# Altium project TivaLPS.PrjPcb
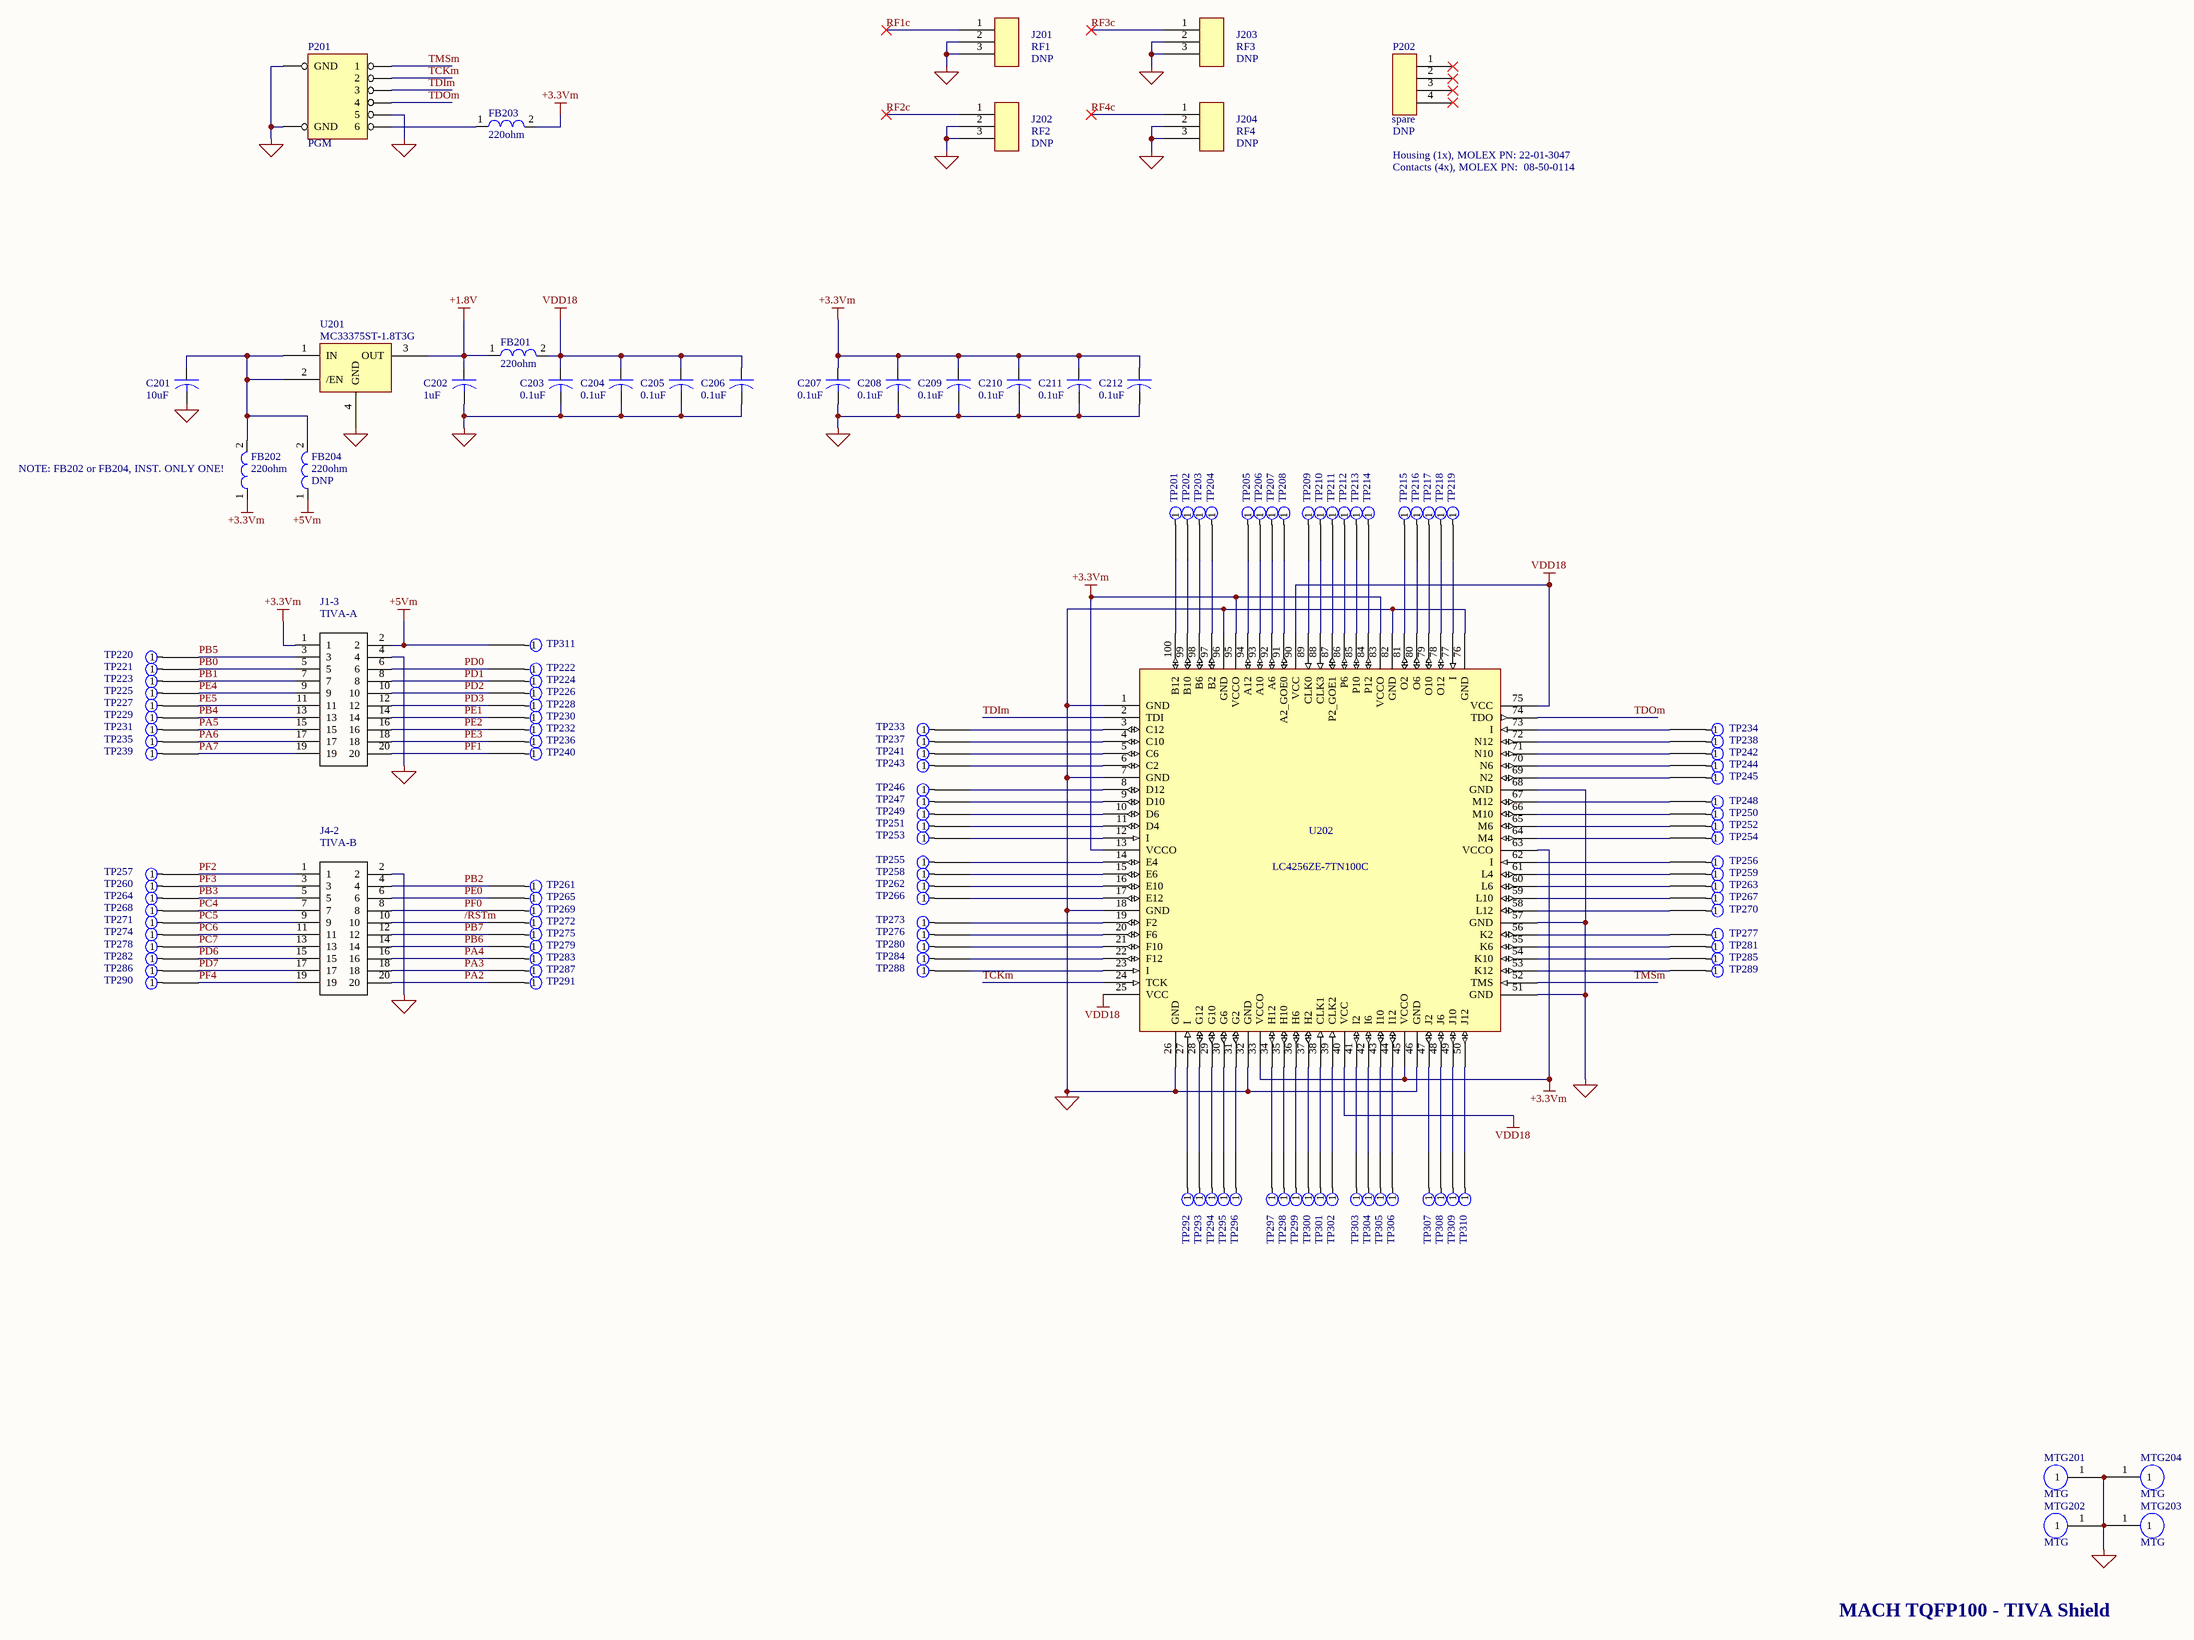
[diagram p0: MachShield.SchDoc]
1 sheet, 141 parts. Net scope: global (net labels, ports and power ports of the same name join across sheets).
Board file: TivaLPS.PcbDoc

## Sheet MachShield.SchDoc
size C

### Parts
C201  10uF  [0805]
C202  1uF  [0805]
C203  0.1uF  [0402]
C204  0.1uF  [0402]
C205  0.1uF  [0402]
C206  0.1uF  [0402]
C207  0.1uF  [0402]
C208  0.1uF  [0402]
C209  0.1uF  [0402]
C210  0.1uF  [0402]
C211  0.1uF  [0402]
C212  0.1uF  [0402]
FB201  220ohm  [0805]
FB202  220ohm  [0805]
FB203  220ohm  [0805]
FB204  220ohm  [0805]
J1-3  TIVA-A  [2X10_PADS]
J4-2  TIVA-B  [2X10_PADS]
J201  RF1  [CONN_SMA_EDGE_062]
J202  RF2  [CONN_SMA_EDGE_062]
J203  RF3  [CONN_SMA_EDGE_062_installed]
J204  RF4  [CONN_SMA_EDGE_062_installed]
MTG201  MTG  [MTG_125]  (no BOM)
MTG202  MTG  [MTG_125]  (no BOM)
MTG203  MTG  [MTG_125]  (no BOM)
MTG204  MTG  [MTG_125]  (no BOM)
P201  PGM  [CON_1.25MM_6P]
P202  spare  [MOLEX-04]
TP201  100  [TP]  (value not drawn)  (no BOM)
TP202  99  [TP]  (value not drawn)  (no BOM)
TP203  98  [TP]  (value not drawn)  (no BOM)
TP204  97  [TP]  (value not drawn)  (no BOM)
TP205  94  [TP]  (value not drawn)  (no BOM)
TP206  93  [TP]  (value not drawn)  (no BOM)
TP207  92  [TP]  (value not drawn)  (no BOM)
TP208  91  [TP]  (value not drawn)  (no BOM)
TP209  89  [TP]  (value not drawn)  (no BOM)
TP210  88  [TP]  (value not drawn)  (no BOM)
TP211  87  [TP]  (value not drawn)  (no BOM)
TP212  86  [TP]  (value not drawn)  (no BOM)
TP213  85  [TP]  (value not drawn)  (no BOM)
TP214  84  [TP]  (value not drawn)  (no BOM)
TP215  81  [TP]  (value not drawn)  (no BOM)
TP216  80  [TP]  (value not drawn)  (no BOM)
TP217  79  [TP]  (value not drawn)  (no BOM)
TP218  78  [TP]  (value not drawn)  (no BOM)
TP219  77  [TP]  (value not drawn)  (no BOM)
TP220  PB5  [TP-TH]  (value not drawn)  (no BOM)
TP221  PB0  [TP-TH]  (value not drawn)  (no BOM)
TP222  PD0  [TP-TH]  (value not drawn)  (no BOM)
TP223  PB1  [TP-TH]  (value not drawn)  (no BOM)
TP224  PD1  [TP-TH]  (value not drawn)  (no BOM)
TP225  PE4  [TP-TH]  (value not drawn)  (no BOM)
TP226  PD2  [TP-TH]  (value not drawn)  (no BOM)
TP227  PE5  [TP-TH]  (value not drawn)  (no BOM)
TP228  PD3  [TP-TH]  (value not drawn)  (no BOM)
TP229  PB4  [TP-TH]  (value not drawn)  (no BOM)
TP230  PE1  [TP-TH]  (value not drawn)  (no BOM)
TP231  PA5  [TP-TH]  (value not drawn)  (no BOM)
TP232  PE2  [TP-TH]  (value not drawn)  (no BOM)
TP233  3  [TP]  (value not drawn)  (no BOM)
TP234  73  [TP]  (value not drawn)  (no BOM)
TP235  PA6  [TP-TH]  (value not drawn)  (no BOM)
TP236  PE3  [TP-TH]  (value not drawn)  (no BOM)
TP237  4  [TP]  (value not drawn)  (no BOM)
TP238  72  [TP]  (value not drawn)  (no BOM)
TP239  PA7  [TP-TH]  (value not drawn)  (no BOM)
TP240  PF1  [TP-TH]  (value not drawn)  (no BOM)
TP241  5  [TP]  (value not drawn)  (no BOM)
TP242  71  [TP]  (value not drawn)  (no BOM)
TP243  6  [TP]  (value not drawn)  (no BOM)
TP244  70  [TP]  (value not drawn)  (no BOM)
TP245  69  [TP]  (value not drawn)  (no BOM)
TP246  8  [TP]  (value not drawn)  (no BOM)
TP247  9  [TP]  (value not drawn)  (no BOM)
TP248  67  [TP]  (value not drawn)  (no BOM)
TP249  10  [TP]  (value not drawn)  (no BOM)
TP250  66  [TP]  (value not drawn)  (no BOM)
TP251  11  [TP]  (value not drawn)  (no BOM)
TP252  65  [TP]  (value not drawn)  (no BOM)
TP253  12  [TP]  (value not drawn)  (no BOM)
TP254  64  [TP]  (value not drawn)  (no BOM)
TP255  14  [TP]  (value not drawn)  (no BOM)
TP256  62  [TP]  (value not drawn)  (no BOM)
TP257  PF2  [TP-TH]  (value not drawn)  (no BOM)
TP258  15  [TP]  (value not drawn)  (no BOM)
TP259  61  [TP]  (value not drawn)  (no BOM)
TP260  PF3  [TP-TH]  (value not drawn)  (no BOM)
TP261  PB2  [TP-TH]  (value not drawn)  (no BOM)
TP262  16  [TP]  (value not drawn)  (no BOM)
TP263  60  [TP]  (value not drawn)  (no BOM)
TP264  PB3  [TP-TH]  (value not drawn)  (no BOM)
TP265  PE0  [TP-TH]  (value not drawn)  (no BOM)
TP266  17  [TP]  (value not drawn)  (no BOM)
TP267  59  [TP]  (value not drawn)  (no BOM)
TP268  PC4  [TP-TH]  (value not drawn)  (no BOM)
TP269  PF0  [TP-TH]  (value not drawn)  (no BOM)
TP270  58  [TP]  (value not drawn)  (no BOM)
TP271  PC5  [TP-TH]  (value not drawn)  (no BOM)
TP272  /RST  [TP-TH]  (value not drawn)  (no BOM)
TP273  19  [TP]  (value not drawn)  (no BOM)
TP274  PC6  [TP-TH]  (value not drawn)  (no BOM)
TP275  PB7  [TP-TH]  (value not drawn)  (no BOM)
TP276  20  [TP]  (value not drawn)  (no BOM)
TP277  56  [TP]  (value not drawn)  (no BOM)
TP278  PC7  [TP-TH]  (value not drawn)  (no BOM)
TP279  PB6  [TP-TH]  (value not drawn)  (no BOM)
TP280  21  [TP]  (value not drawn)  (no BOM)
TP281  55  [TP]  (value not drawn)  (no BOM)
TP282  PD6  [TP-TH]  (value not drawn)  (no BOM)
TP283  PA4  [TP-TH]  (value not drawn)  (no BOM)
TP284  22  [TP]  (value not drawn)  (no BOM)
TP285  54  [TP]  (value not drawn)  (no BOM)
TP286  PD7  [TP-TH]  (value not drawn)  (no BOM)
TP287  PA3  [TP-TH]  (value not drawn)  (no BOM)
TP288  23  [TP]  (value not drawn)  (no BOM)
TP289  53  [TP]  (value not drawn)  (no BOM)
TP290  PF4  [TP-TH]  (value not drawn)  (no BOM)
TP291  PA2  [TP-TH]  (value not drawn)  (no BOM)
TP292  27  [TP]  (value not drawn)  (no BOM)
TP293  28  [TP]  (value not drawn)  (no BOM)
TP294  29  [TP]  (value not drawn)  (no BOM)
TP295  30  [TP]  (value not drawn)  (no BOM)
TP296  31  [TP]  (value not drawn)  (no BOM)
TP297  34  [TP]  (value not drawn)  (no BOM)
TP298  35  [TP]  (value not drawn)  (no BOM)
TP299  36  [TP]  (value not drawn)  (no BOM)
TP300  37  [TP]  (value not drawn)  (no BOM)
TP301  38  [TP]  (value not drawn)  (no BOM)
TP302  39  [TP]  (value not drawn)  (no BOM)
TP303  41  [TP]  (value not drawn)  (no BOM)
TP304  42  [TP]  (value not drawn)  (no BOM)
TP305  43  [TP]  (value not drawn)  (no BOM)
TP306  44  [TP]  (value not drawn)  (no BOM)
TP307  47  [TP]  (value not drawn)  (no BOM)
TP308  48  [TP]  (value not drawn)  (no BOM)
TP309  49  [TP]  (value not drawn)  (no BOM)
TP310  50  [TP]  (value not drawn)  (no BOM)
TP311  PD0  [TP-TH]  (value not drawn)  (no BOM)
U201  MC33375ST-1.8T3G  [SOT223]
U202  LC4256ZE-7TN100C  [SQFP50P1600X1600X245-100N]

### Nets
+1.8V: C202.1 FB201.1 U201.3(OUT)
+3.3Vm: C207.1 C208.1 C209.1 C210.1 C211.1 C212.1 FB202.1 FB203.2 J1-3.1 U202.13(VCCO) U202.33(VCCO) U202.45(VCCO) U202.63(VCCO) U202.83(VCCO) U202.95(VCCO)
+5Vm: FB204.1 J1-3.2 TP311.1
GNDm: C201.2 C202.2 C203.2 C204.2 C205.2 C206.2 C207.2 C208.2 C209.2 C210.2 C211.2 C212.2 J1-3.4 J4-2.2 J201.2 J201.3 J202.2 J202.3 J203.2 J203.3 J204.2 J204.3 MTG201.1 MTG202.1 MTG203.1 MTG204.1 P201.5 P201.7(GND) P201.8(GND) U201.4(GND) U202.1(GND) U202.7(GND) U202.18(GND) U202.26(GND) U202.32(GND) U202.46(GND) U202.51(GND) U202.57(GND) U202.68(GND) U202.76(GND) U202.82(GND) U202.96(GND)
VDD18: C203.1 C204.1 C205.1 C206.1 FB201.2 U202.25(VCC) U202.40(VCC) U202.75(VCC) U202.90(VCC)
/RSTm: J4-2.10 TP272.1
PA2: J4-2.20 TP291.1
PA3: J4-2.18 TP287.1
PA4: J4-2.16 TP283.1
PA5: J1-3.15 TP231.1
PA6: J1-3.17 TP235.1
PA7: J1-3.19 TP239.1
PB0: J1-3.5 TP221.1
PB1: J1-3.7 TP223.1
PB2: J4-2.4 TP261.1
PB3: J4-2.5 TP264.1
PB4: J1-3.13 TP229.1
PB5: J1-3.3 TP220.1
PB6: J4-2.14 TP279.1
PB7: J4-2.12 TP275.1
PC4: J4-2.7 TP268.1
PC5: J4-2.9 TP271.1
PC6: J4-2.11 TP274.1
PC7: J4-2.13 TP278.1
PD0: J1-3.6 TP222.1
PD1: J1-3.8 TP224.1
PD2: J1-3.10 TP226.1
PD3: J1-3.12 TP228.1
PD6: J4-2.15 TP282.1
PD7: J4-2.17 TP286.1
PE0: J4-2.6 TP265.1
PE1: J1-3.14 TP230.1
PE2: J1-3.16 TP232.1
PE3: J1-3.18 TP236.1
PE4: J1-3.9 TP225.1
PE5: J1-3.11 TP227.1
PF0: J4-2.8 TP269.1
PF1: J1-3.20 TP240.1
PF2: J4-2.1 TP257.1
PF3: J4-2.3 TP260.1
PF4: J4-2.19 TP290.1
RF1c: J201.1
RF2c: J202.1
RF3c: J203.1
RF4c: J204.1
TCKm: P201.2 U202.24(TCK)
TDIm: P201.3 U202.2(TDI)
TDOm: P201.4 U202.74(TDO)
TMSm: P201.1 U202.52(TMS)
NetC201_1: C201.1 FB202.2 FB204.2 U201.1(IN) U201.2(/EN)
NetFB203_1: FB203.1 P201.6
NetTP201_1: TP201.1 U202.100(B12)
NetTP202_1: TP202.1 U202.99(B10)
NetTP203_1: TP203.1 U202.98(B6)
NetTP204_1: TP204.1 U202.97(B2)
NetTP205_1: TP205.1 U202.94(A12)
NetTP206_1: TP206.1 U202.93(A10)
NetTP207_1: TP207.1 U202.92(A6)
NetTP208_1: TP208.1 U202.91(A2_GOE0)
NetTP209_1: TP209.1 U202.89(CLK0)
NetTP210_1: TP210.1 U202.88(CLK3)
NetTP211_1: TP211.1 U202.87(P2_GOE1)
NetTP212_1: TP212.1 U202.86(P6)
NetTP213_1: TP213.1 U202.85(P10)
NetTP214_1: TP214.1 U202.84(P12)
NetTP215_1: TP215.1 U202.81(O2)
NetTP216_1: TP216.1 U202.80(O6)
NetTP217_1: TP217.1 U202.79(O10)
NetTP218_1: TP218.1 U202.78(O12)
NetTP219_1: TP219.1 U202.77(I)
NetTP233_1: TP233.1 U202.3(C12)
NetTP234_1: TP234.1 U202.73(I)
NetTP237_1: TP237.1 U202.4(C10)
NetTP238_1: TP238.1 U202.72(N12)
NetTP241_1: TP241.1 U202.5(C6)
NetTP242_1: TP242.1 U202.71(N10)
NetTP243_1: TP243.1 U202.6(C2)
NetTP244_1: TP244.1 U202.70(N6)
NetTP245_1: TP245.1 U202.69(N2)
NetTP246_1: TP246.1 U202.8(D12)
NetTP247_1: TP247.1 U202.9(D10)
NetTP248_1: TP248.1 U202.67(M12)
NetTP249_1: TP249.1 U202.10(D6)
NetTP250_1: TP250.1 U202.66(M10)
NetTP251_1: TP251.1 U202.11(D4)
NetTP252_1: TP252.1 U202.65(M6)
NetTP253_1: TP253.1 U202.12(I)
NetTP254_1: TP254.1 U202.64(M4)
NetTP255_1: TP255.1 U202.14(E4)
NetTP256_1: TP256.1 U202.62(I)
NetTP258_1: TP258.1 U202.15(E6)
NetTP259_1: TP259.1 U202.61(L4)
NetTP262_1: TP262.1 U202.16(E10)
NetTP263_1: TP263.1 U202.60(L6)
NetTP266_1: TP266.1 U202.17(E12)
NetTP267_1: TP267.1 U202.59(L10)
NetTP270_1: TP270.1 U202.58(L12)
NetTP273_1: TP273.1 U202.19(F2)
NetTP276_1: TP276.1 U202.20(F6)
NetTP277_1: TP277.1 U202.56(K2)
NetTP280_1: TP280.1 U202.21(F10)
NetTP281_1: TP281.1 U202.55(K6)
NetTP284_1: TP284.1 U202.22(F12)
NetTP285_1: TP285.1 U202.54(K10)
NetTP288_1: TP288.1 U202.23(I)
NetTP289_1: TP289.1 U202.53(K12)
NetTP292_1: TP292.1 U202.27(I)
NetTP293_1: TP293.1 U202.28(G12)
NetTP294_1: TP294.1 U202.29(G10)
NetTP295_1: TP295.1 U202.30(G6)
NetTP296_1: TP296.1 U202.31(G2)
NetTP297_1: TP297.1 U202.34(H12)
NetTP298_1: TP298.1 U202.35(H10)
NetTP299_1: TP299.1 U202.36(H6)
NetTP300_1: TP300.1 U202.37(H2)
NetTP301_1: TP301.1 U202.38(CLK1)
NetTP302_1: TP302.1 U202.39(CLK2)
NetTP303_1: TP303.1 U202.41(I2)
NetTP304_1: TP304.1 U202.42(I6)
NetTP305_1: TP305.1 U202.43(I10)
NetTP306_1: TP306.1 U202.44(I12)
NetTP307_1: TP307.1 U202.47(J2)
NetTP308_1: TP308.1 U202.48(J6)
NetTP309_1: TP309.1 U202.49(J10)
NetTP310_1: TP310.1 U202.50(J12)

Not connected (* = marked no-connect by the designer): P202 1(_)* 2(_)* 3(_)* 4(_)*

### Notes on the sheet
- Housing (1x), MOLEX PN: 22-01-3047
- Contacts (4x), MOLEX PN:  08-50-0114
- (near FB202) NOTE: FB202 or FB204, INST. ONLY ONE!
- MACH TQFP100 - TIVA Shield

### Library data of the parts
C201 = CAP 0805: CAP, MLCC, 0805, X5R, 50V, 10uF; MPN: CL21A106KBYQNNE; MFR: Samsung
C202 = CAP 0805: CAP, MLCC, 0805, X7R, 50V, 1uF; MPN: CL21B105KBFNNNF; MFR: Samsung
C203-C212 = CAP 0805: CAP, MLCC, 0402, X7R, 50V, 0.1uF; MPN: 04025C104KAT2A; MFR: AVX
FB201-FB204 = FB: BD, FRITE, 0805, 2A, 220ohm; MPN: FBMH2012HM221-T; MFR: Taiyo Yuden
J1-3 J4-2 = CON, TH, 2x10: HDR, TH, 2x10; MPN: 67997-410HLF; MFR: Amphenol FCI
J201-J204 = CON_3P: CON, SIP, 3 POS; MPN: EMPCB.SMAFSTJ.B.HT; MFR: Taoglas
P201 = HEADER-6-PIN-RT-ANG: CON, 6POS, 1.25MM, SMD; MPN: 53398-0671; MFR: Molex; ALTPN: 53398-0671 (V), or 53261-0671 (RA)
P202 = CON_4P: CON, SIP, 4 POS; MFR: Molex
TP201-TP311 = TP
U201 = MC33375ST-3.3T3G: IC, VREG, LDO, SOT-223; MFR: OnSemi
U202 = LC4256ZE-7TN100C: IC, CPLD, 100TQFP, LC4256; MFR: Lattice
